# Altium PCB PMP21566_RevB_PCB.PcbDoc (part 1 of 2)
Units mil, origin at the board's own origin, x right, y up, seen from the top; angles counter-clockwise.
Board outline 4339 x 2011 mil, 4 copper layers (Top Layer1, Layer2, Layer3, Bottom Layer4), stack 60.4 mil thick; 97 components, 43 nets, 239 pads, 687 vias.
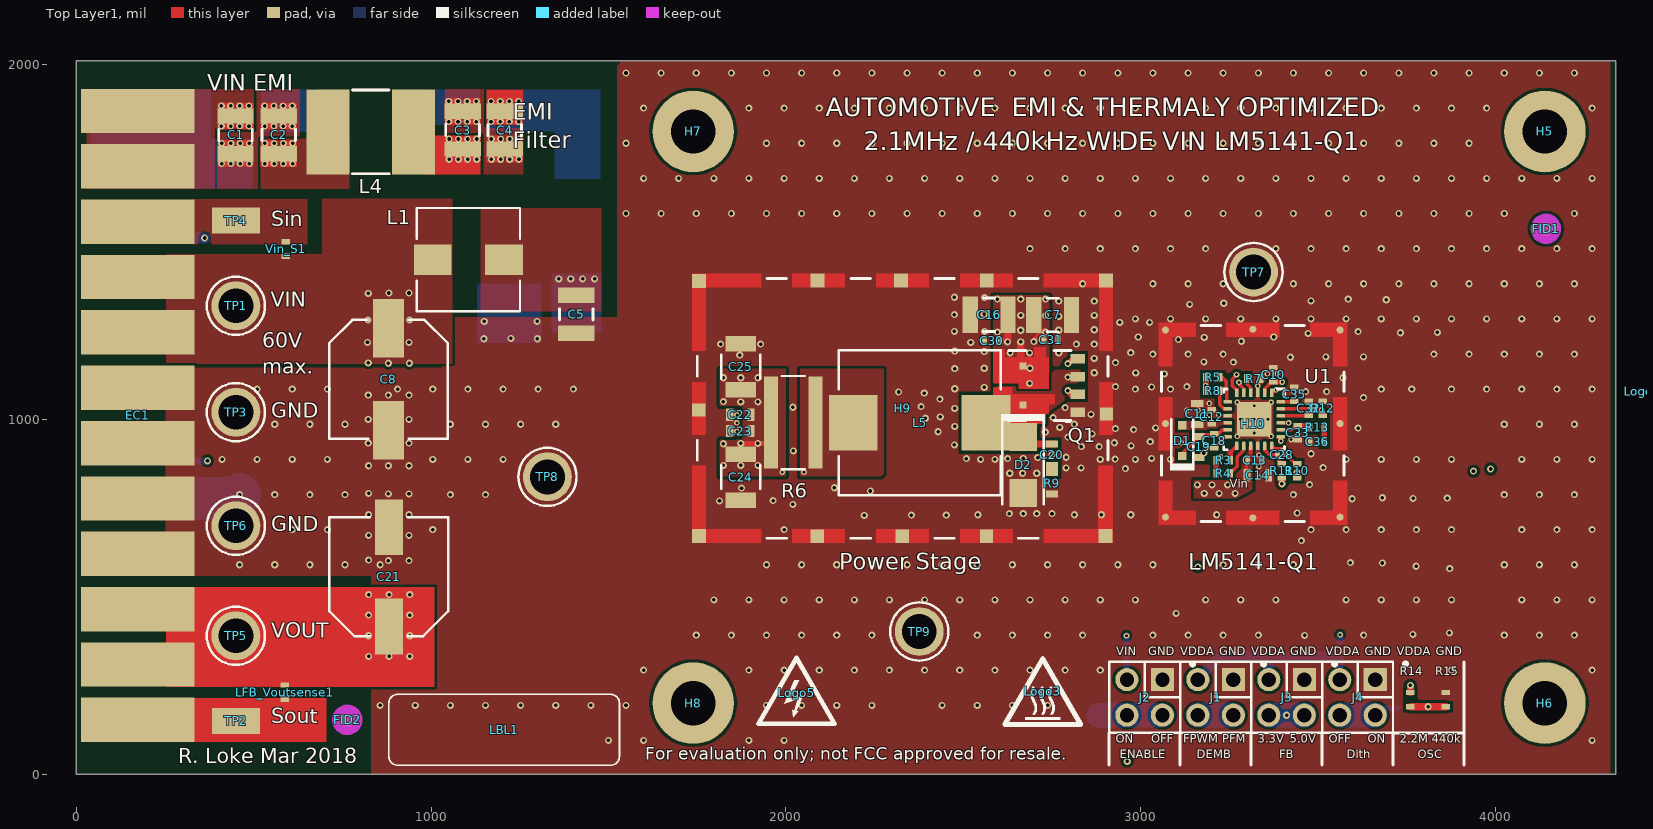
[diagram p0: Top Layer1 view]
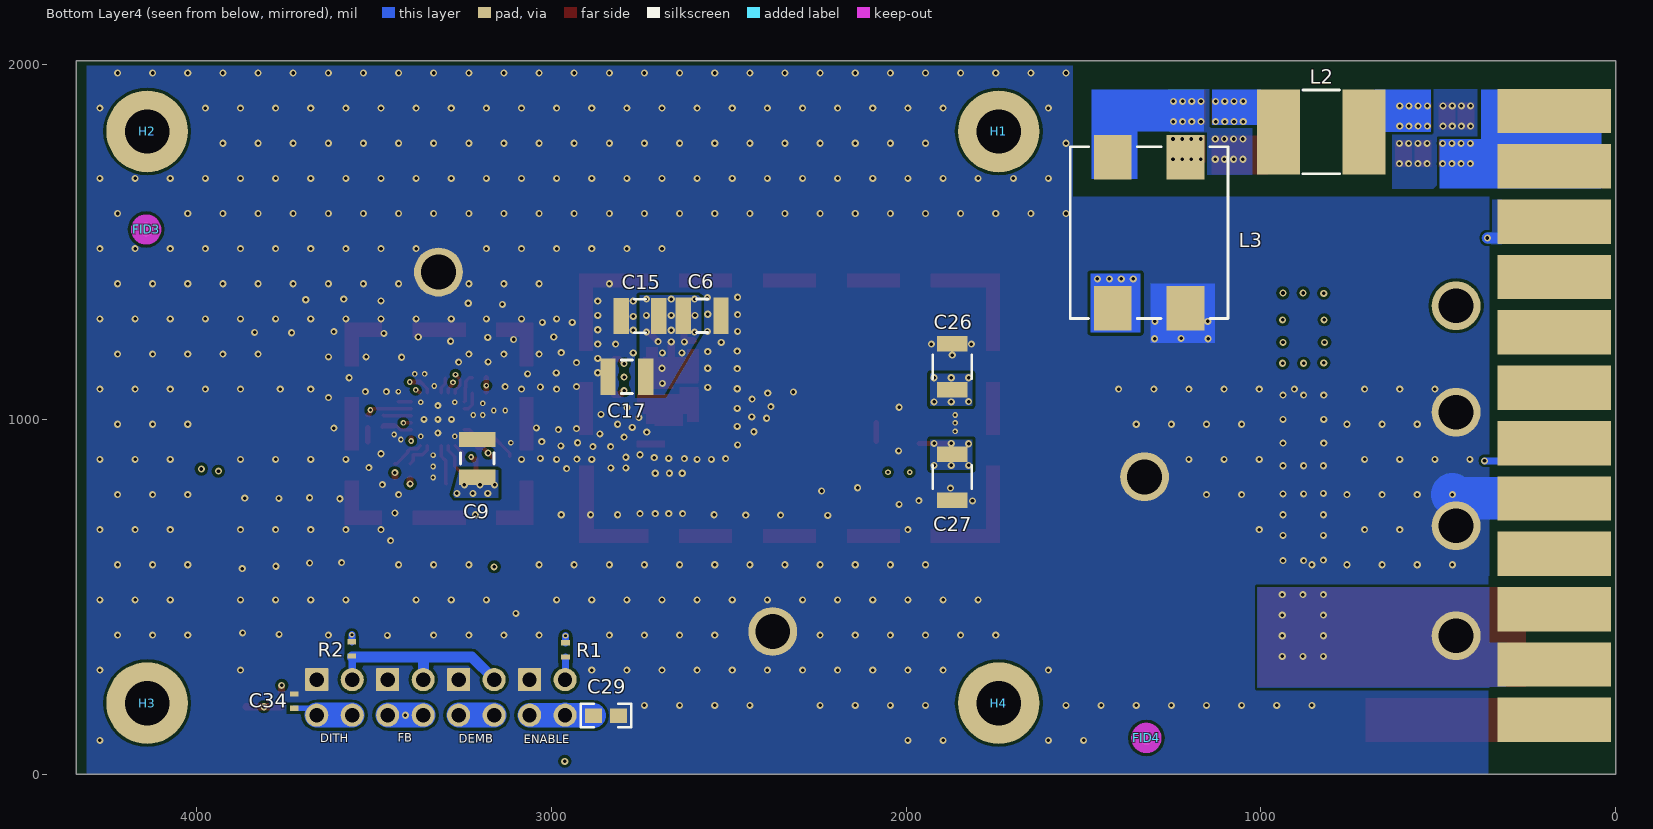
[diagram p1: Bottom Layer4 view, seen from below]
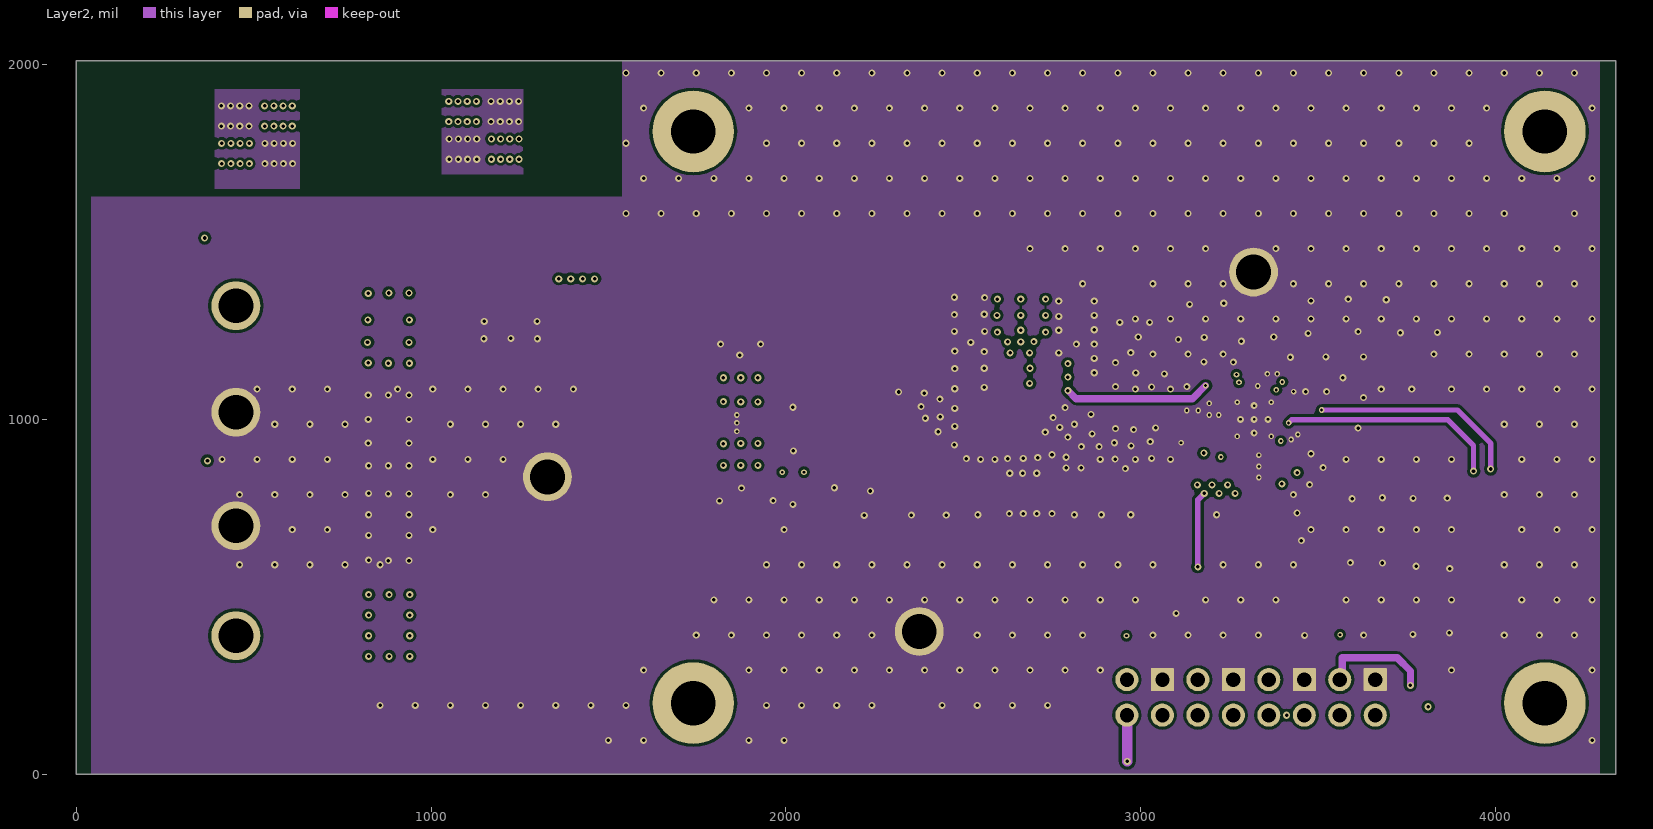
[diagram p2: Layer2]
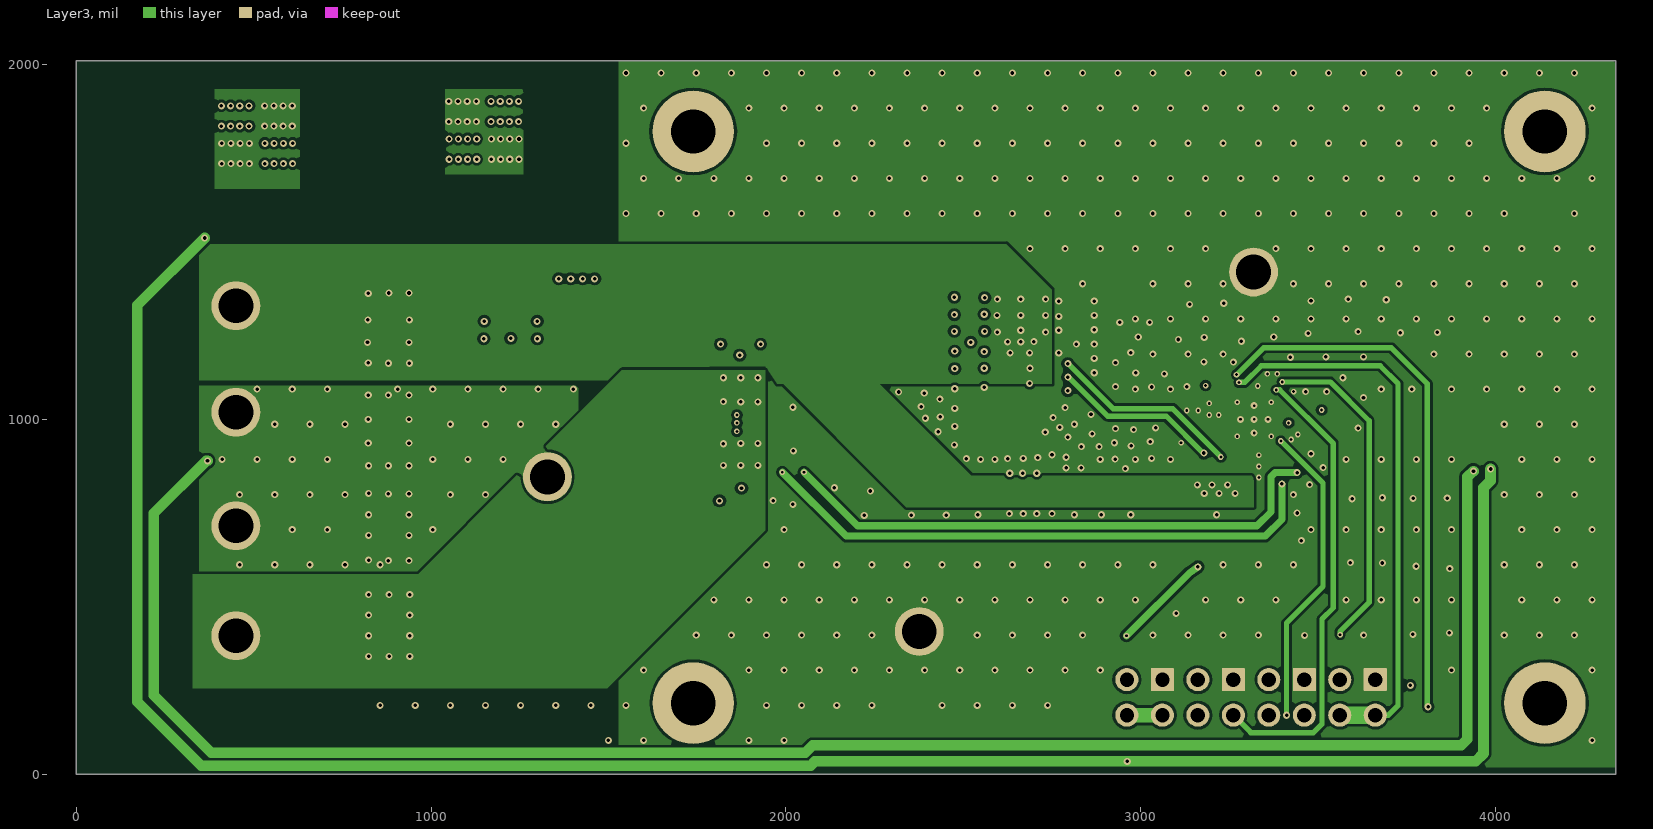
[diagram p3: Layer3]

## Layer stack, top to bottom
Top Solder: solder mask 0.4, Solder Resist, Dk 3.5
Top Layer1: signal copper 2.8
Dielectric1: core 5, FR-4, Dk 4.2
Layer2: signal copper 1.4
Dielectric 3: prepreg 42, FR4, Dk 4.2
Layer3: signal copper 1.4
Dielectric 2: core 5, FR4, Dk 4.2
Bottom Layer4: signal copper 2.8
Bottom Solder: solder mask 0.4, Solder Resist, Dk 3.5

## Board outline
0,0 0,2011 4339,2011 4339,0

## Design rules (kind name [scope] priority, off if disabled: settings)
Clearance Clearance_Poly [InPolygon] p1: gap=8 ignorepadtopadclearanceinfootprint=FALSE
Clearance Clearance_1 [All] p2: gap=6 ignorepadtopadclearanceinfootprint=FALSE
ComponentClearance [All] p1: gap=10 collisioncheckmode=3 verticalgap=-1 showdistances=TRUE
FabricationTestPointUsage TestPointUsage [All] p1: valid=0 allowmultiple=FALSE
FabricationTestpoint Testpoint [All] p1: side=3 testpointundercomponent=TRUE minsize=40 maxsize=100 preferedsize=60 minholesize=20 maxholesize=40 preferedholesize=32 testpointgrid=1 allowsidetop=TRUE allowsidebottom=TRUE usegrid=TRUE gridtolerance=0.01
HoleSize [All] p1: absolutevalues=TRUE maxlimit=247 minlimit=7.87 maxpercent=80.000 minpercent=20.000
MinimumSolderMaskSliver [All] p1: minsoldermaskwidth=3
PasteMaskExpansion PasteMaskExpansion_1 [InComponent('P1')] p1: expansion=-150
PasteMaskExpansion [All] p2: expansion=0
PlaneConnect [All] p1: planeconnectstyle=Relief reliefexpansion=15 reliefentries=4 reliefconductorwidth=5 reliefairgap=5
PolygonConnect [All] p1: connectstyle=Direct reliefconductorwidth=10 reliefentries=4 polygonreliefangle="90 Angle" airgapwidth=10
RoutingVias [All] p1: holewidth=10 width=20 viastyle="Through Hole" minholewidth=7.87 minwidth=16 maxholewidth=15 maxwidth=50
SilkToBoardRegionClearance [Not ((IsComment or IsDesignator) And (Hide <> 'False')) and not InRegion(1000,500,4000,800)] p1:
SilkToSilkClearance [All] p1: silktosilkclearance=2
SilkToSolderMaskClearance SilkscreenOverComponentPads [IsPad] p1: minsilkscreentomaskgap=1 clearancetoexposedcopper=TRUE
SolderMaskExpansion [All] p1: expansion=5
UnRoutedNet [All] p1: checkbadconnections=TRUE
Width [All] p1: maxlimit=150 minlimit=5 preferedwidth=10
19 further rules are at their usual default settings.

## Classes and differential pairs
component class PMP_LM5141_2.1MHZ_RL_RevB: "As short as possble" C1 C2 C3 C4 C5 C6 C7 C8 C9 C10 C11 C12 C13 C14 C15 C16 C17 C18 C19 C20 C21 C22 C23 C24 C25 C26 C27 C28 C29 C30 C31 C32 C33 C34 C35 C36 "Close to Q1" "Close to Q1S" "Close to Q3" "Close to Q3S" "Close to Q5" "Close to Q6" D1 D2 H9 H10 J1 J2 J3 J4 L1 L2 L3 L4 L5 L6 LFB_Voutsense1 Q1 R1 R2 R3 R4 R5 R6 R7 R8 R9 R10 R11 R12 R13 R14 R15 R25 R26 TP1 TP2 TP3 TP4 TP5 TP6 TP7 TP8 TP9 TP14 U1 Vin_S1 ZX1 ZX2 ZX3
component class PMP_LM5141_2.1MHZ_RL_RevB_HW: !PCB1 FID1 FID2 FID3 FID4 H1 H2 H3 H4 H5 H6 H7 H8 LBL1 Logo1 Logo2 Logo3 Logo4 Logo5
component class FiducialMark: FID1 FID2 FID3 FID4
component class Label: LBL1
component class AssemblyNote: ZX1 ZX2 ZX3
component class Header: J1 J2 J3 J4

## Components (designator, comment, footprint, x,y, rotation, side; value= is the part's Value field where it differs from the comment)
C1 "GRM32ER71J106KA12L" 1210_270L 449,1801.49 r270 top value=10uF
C2 "GRM32ER71J106KA12L" 1210_270L 571,1801.49 r270 top value=10uF
C3 "GRM32ER71J106KA12L" 1210_270L 1089,1815 r270 top value=10uF
C4 "GRM32ER71J106KA12L" 1210_270L 1208,1815 r270 top value=10uF
C5 "GRM32ER71J106KA12L" 1210_270L 1409,1296 r270 top value=10uF
C6 "GRM32ER71J106KA12L" 1210_270L 2575,1292 r180 bottom value=10uF
C7 "GRM32ER71J106KA12L" 1210_270L 2752,1294 r0 top value=10uF
C8 "EMVE630ADA470MHA0G" CAPSMT_62_HA0 880,1113 r270 top value=47uF
C9 "GRM32ER71J106KA12L" 1210_270L 3209,890 r90 bottom value=10uF
C10 "C0402C104K4RACAUTO" 0402S 3373,1126 r270 top value=0.1uF
C11 "GRM188Z71C475KE21D" 0603S 3159,1015 r90 top value=4.7uF
C12 "C0402C104K4RACAUTO" 0402S 3200,1007 r270 top value=0.1uF
C13 "GRM155R72A472KA01D" 0402S 3321,884 r0 top value=4700pF
C14 "GCJ188R72A104KA01D" 0603S 3330,842 r0 top value=0.1uF
C15 "GRM32ER71J106KA12L" 1210_270L 2750,1291 r0 bottom value=10uF
C16 "GRM32ER71J106KA12L" 1210_270L 2573,1295 r180 top value=10uF
C17 "GRM32ER71J106KA12L" 1210_270L 2787,1120 r0 bottom value=10uF
C18 "C1005X7R1H683K050BB" 0402S 3207,939 r270 top value=0.068uF
C19 "CGA3E3X7R1H474K080AB" 0603S 3163,922 r90 top value=0.47uF
C20 "06031C102JAT2A" 0603S 2750,900 r270 top value=1000pF
C21 "EEE-FK1E221P" SM_RADIAL_F 881,556 r90 top value=220uF
C22 "GRM188Z71C475KE21D" 0603S 1872,1013 r180 top value=4.7uF
C23 "GRM188Z71C475KE21D" 0603S 1872,967 r180 top value=4.7uF
C24 "LMK325ABJ107MMHT" 1210_280 1873,837 r270 top value=100uF
C25 "LMK325ABJ107MMHT" 1210_280 1873,1148 r90 top value=100uF
C26 "LMK325ABJ107MMHT" 1210_280 1870,1148 r90 bottom value=100uF
C27 "LMK325ABJ107MMHT" 1210_280 1870,837 r270 bottom value=100uF
C28 "GRM0335C1H330JA01D" 0201L 3397,900 r180 top value=33pF
C29 "1.5ms delay at 12Vin" 0603M 2846,165 r180 bottom value=0.022uF
C30 "GRM155R72A472KA01D" 0402S 2580,1222 r180 top value=4700pF
C31 "GRM155R72A472KA01D" 0402S 2747,1224 r0 top value=4700pF
C32 "C1005X7R1H683K050BB" 0402S 3473,1031 r90 top value=0.068uF
C33 "GRM1555C1H220JA01D" 0402S 3443,962 r270 top value=22pF
C34 "C0402C103J5RACTU" 0402S 3725,206 r270 bottom value=0.01uF
C35 "CGA2B3X7R1H103K050BB" 0402S 3433,1071 r90 top value=0.01uF
C36 "CGA2B3X7R1H103K050BB" 0402S 3497,937 r180 top value=0.01uF
D1 "PMEG6010CEJ,115" SOD-323F 3117,940 r90 top value=60V
D2 "SSA210" SMA 2668.98,871.26 r270 top value=100V
EC1 "305-024-521-201" Edge_Connector_EDAC_12x2 146,1011 r270 top
FID1 "Fiducial" Fiducial10-20 4142,1537 r0 top
FID2 "Fiducial" Fiducial10-20 764,153 r0 top
FID3 "Fiducial" Fiducial10-20 4142,1535 r180 bottom
FID4 "Fiducial" Fiducial10-20 1323,102 r180 bottom
H1 "1902C" Keystone_1902C 1738.62,1811.26 r0 bottom
H2 "1902C" Keystone_1902C 4138.62,1811.26 r0 bottom
H3 "1902C" Keystone_1902C 4138.62,200.26 r0 bottom
H4 "1902C" Keystone_1902C 1738.98,200.26 r0 bottom
H5 "PMSSS 440 0025 PH" B_F_PMSSS4400025PH 4138.98,1811.26 r270 top
H6 "PMSSS 440 0025 PH" B_F_PMSSS4400025PH 4138.98,200.26 r270 top
H7 "PMSSS 440 0025 PH" B_F_PMSSS4400025PH 1738.98,1811.26 r270 top
H8 "PMSSS 440 0025 PH" B_F_PMSSS4400025PH 1738.98,200.26 r270 top
H9 "BMI-S-209-F" Laird_BMI-S-209-F 2329,1031 r180 top
H10 "BMI-S-201-F" Laird_BMI-S-201-F 3316,988 r0 top
J1 "DEMB" TSW-102-07-G-D 3211.07,216.25 r180 top
J2 "EN" TSW-102-07-G-D 3011.07,216.25 r180 top
J3 "FB" TSW-102-07-G-D 3411.07,216.25 r180 top
J4 "Dith" TSW-102-07-G-D 3611.07,216.25 r180 top
L1 "744314150" WE-HCI_7050 1105,1450 r180 top value=1.5uH
L2 "HR2220V801R-10" 2220_390 830,1810 r0 bottom value="800 ohm"
L3 "ACM1211-701-2PL-TL01" TDK_ACM1211 1315,1526 r180 bottom
L4 "HR2220V801R-10" 2220_390 830,1810 r0 top value="800 ohm"
L5 "IHLP4040DZER2R0M11" IHLP-4040DZ 2376.98,990.26 r180 top value=2uH
LBL1 "" Label_650x200 1206,125 r0 top
LFB_Voutsense1 "BLM15AX100SN1D" 0402S 588,231 r270 top value="10 ohm"
Logo1 "FCC disclaimer" FCC_disclaimer 4415,1079 r90 top
Logo3 "CAUTION HOT SURFACE" IEC_HotSurface_Small 2724,233 r0 top
Logo5 "DANGER HIGH VOLTAGE" IEC_HighVoltage_Small 2030,230 r0 top
Q1 "SQJB60EP-T1_GE3" PowerPAK_SO-8L_Dual 2715.98,1095.26 r180 top value=60V
R1 "CRCW0402100KFKED" 0402S 2960,350 r90 bottom value=100k
R2 "CRCW0402100KFKED" 0402S 3562,353 r90 bottom value=100k
R3 "RMCF0402JT10R0" 0402S 3232,885 r180 top value=10.0
R4 "RK73Z1ETTP" 0402S 3232,848 r180 top value=0
R5 "RK73Z1ETTP" 0402S 3203,1118 r180 top value=0
R6 "KRL6432E-M-R006-F-T1" 2512_WIDE 2021,991 r180 top value=0.006
R7 "2.1MHz" 0402S 3319,1115 r0 top value=51.1k
R8 "RK73Z1ETTP" 0402S 3203,1080 r180 top value=0
R9 "CRCW06031R00JNEA" 0603S 2750,820 r90 top value=1.0
R10 "RMCF0402FT49R9" 0402S 3441,855 r90 top value=49.9
R11 "RK73Z1ETTP" 0402S 3398,855 r90 top value=0
R12 "Turns ON at 6Vin" 0402S 3513,1031 r270 top value=49.9k
R13 "CRCW04025K49FKED" 0402S 3497,977 r180 top value=5.49k
R14 "2.2MHz" 0402S 3760,210 r90 top value=0
R15 "DNP" 0402S 3860,210 r90 top value=0
TP1 "Vin" Keystone1598-2 450,1320 r180 top value=Triple
TP2 "S1751-46" Harwin_S1751-46 450,150 r0 top
TP3 "GND" Keystone1598-2 450,1020 r180 top value=Triple
TP4 "S1751-46" Harwin_S1751-46 450,1560 r180 top
TP5 "Vout" Keystone1598-2 450,390 r180 top value=Triple
TP6 "GND" Keystone1598-2 450,700 r180 top value=Triple
TP7 "GND" Keystone1598-2 3318,1415 r90 top value=Triple
TP8 "GND" Keystone1598-2 1328,838 r90 top value=Triple
TP9 "GND" Keystone1598-2 2376,402 r90 top value=Triple
U1 "LM5141QRGERQ1" RGE0024J 3320,1000 r270 top
Vin_S1 "BLM15AX100SN1D" 0402S 590,1480 r270 top value="10 ohm"
ZX1 "VIN = 9...36V DC, 5.5V...42V Abs max." AssemblyNote 170,2390 r0 top
ZX2 "VOUT = 3.3VDC at 10A" AssemblyNote 170,2460 r0 top
ZX3 "Fsw = 2.2MHz" AssemblyNote 170,2530 r0 top

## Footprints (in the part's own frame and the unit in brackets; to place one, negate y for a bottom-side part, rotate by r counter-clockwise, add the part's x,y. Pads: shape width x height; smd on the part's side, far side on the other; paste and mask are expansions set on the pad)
0201L [mm] "Data from Kemet datasheet CC101_COM dated 7/28/11"
  rect 0.36x0.32 smd mask+0.048: 1(-0.28,0) 2(0.28,0)
  body extent -0.31,-0.16 0.31,0.16, height 0.26
0402S [mil] "Based on C0402S footprint from PADS legacy"
  rect 15x24 smd: 1(-20,0) 2(20,0)
  body extent -22,-12 22,12, height 24
0603M [mm] "0603 from SM-752 data"
  rect 1.2x1.05 smd: 1(-0.9,0) 2(0.9,0)
  silkscreen extent -1.82,-0.84 1.82,0.84, body extent -0.87,-0.47 0.87,0.47, height 1
0603S [mil]
  rect 20x35 smd: 1(-30,0) 2(30,0)
  body extent -34,-19 34,19, height 39
1210_270L [mm] "1210"
  rect 1.1x2.6 smd: 1(-1.35,0) 2(1.35,0)
  silkscreen extent -0.4,-1.2 0.4,1.2, body extent -1.7,-1.35 1.7,1.35, height 2.7
1210_280 [mm] "SMD, 2-Leads, Body 3.6x2.8mm, Height 2.8mm"
  rect 1.1x2.2 smd: 1(-1.65,0) 2(1.65,0)
  silkscreen extent -0.84,-1.4 0.84,1.4, body extent -1.8,-1.4 1.8,1.4, height 2.8
2220_390 [mm] "Laird recommended land pattern"
  rrect3% 3.07x6.1 smd: 1(-3.06,0) 2(3.06,0)
  silkscreen extent -1.3,-3 1.3,3, body extent -2.8,-2.54 2.79,2.54, height 3.9
2512_WIDE [mm] "Ohmite recommended land pattern"
  rect 1x6.6 smd: 1(-1.6,0) 2(1.6,0)
  silkscreen extent -0.82,-3.32 0.82,3.35, body extent -1.65,-3.25 1.65,3.25, height 0.7
AssemblyNote [mil] "Assembly Note"
B_F_PMSSS4400025PH [mil] "MACHINE SCREW PAN PHILLIPS 4-40"
  round 230 hole 125: 1(0,0)
  body extent -109,-109 110,110, height 79
CAPSMT_62_HA0 [mm] "8 x 10mm:  Chemi-Con HA0"
  rect 4.2x2.2 smd: 1(-3.65,0) 2(3.65,0)
  silkscreen extent -4.25,-4.25 4.25,4.25, body extent -4.25,-4.25 4.25,4.25, height 10.5
Edge_Connector_EDAC_12x2 [mil] "Footprint to mate to EDAC 305 Series Edge connector"
  rect 125x320 smd far side paste-260: 1(858,27) 2(702,27) 3(546,27) 4(390,27) 5(234,27) 6(78,27) 7(-78,27) 8(-234,27) 9(-390,27) 10(-546,27) 11(-702,27) 12(-858,27)
  rect 125x320 smd paste-260: A(858,27) B(702,27) C(546,27) D(390,27) E(234,27) F(78,27) H(-78,27) J(-234,27) K(-390,27) L(-546,27) M(-702,27) N(-858,27)
FCC_disclaimer [mil]
Fiducial10-20 [mm]
  round 1 smd mask+0.5: 1(0,0)
  Top Layer1 keep-out circle w1.178: c0,0 r0.5
Harwin_S1751-46 [mm] "Test Point, Body 3.25x1.65mm"
  rect 3.45x1.85 smd: 1(0,0)
  body extent -1.62,-0.82 1.63,0.82, height 2.05
IEC_HighVoltage_Small [mil]
  silkscreen extent -107,-88 107,97
IEC_HotSurface_Small [mil]
  silkscreen extent -107,-93 107,92
IHLP-4040DZ [mm] "Vishay Dale recommended land pattern.  Document 34192 rev 04-Jul-08"
  rect 3.5x4 smd: 1(-4.75,0) 2(4.75,0)
  silkscreen extent -5.8,-5.2 5.8,5.2, body extent -5.75,-5.15 5.75,5.15, height 4
Keystone1598-2 [mm] "Triple Turret"
  round 3.5 hole 2.5: 1(0,0)
  silkscreen extent -2.08,-2.08 2.08,2.08, body extent -1.6,-1.6 1.59,1.6, height 7.72
Keystone_1902C [mil] "Hex Standoff, 4-40 threaded, nylon"
  round 1 on Mech4: 0(0,0)
  body extent -145,-126 146,126, height 501
Label_650x200 [mil] "Thermal Transfer Label"
  round 1 on Mech13: 0(0,0)
  silkscreen extent -325,-100 325,100, body extent -325,-100 325,100, height 1
Laird_BMI-S-201-F [mm] "SMD, 8-Leads, Body 13.06x14.02mm"
  round 0.5 smd: 1(-6.25,-6.694) 1(-6.25,0) 1(-6.25,6.694) 1(0,-6.75) 1(0,6.75) 1(6.25,-6.694) 1(6.25,0) 1(6.25,6.694)
  Top Layer1 region: -1.9,-7.23 -1.9,-6.23 1.9,-6.23 1.9,-7.23
  Top Layer1 region: 4.1,-7.23 4.1,-6.23 5.75,-6.23 5.75,-4.1 6.75,-4.1 6.75,-7.23
  Top Layer1 region: 5.75,-1.9 6.75,-1.9 6.75,1.9 5.75,1.9
  Top Layer1 region: 4.1,6.23 4.1,7.23 6.75,7.23 6.75,4.1 5.75,4.1 5.75,6.23
  Top Layer1 region: -1.9,6.23 1.9,6.23 1.9,7.23 -1.9,7.23
  Top Layer1 region: -6.75,4.1 -5.75,4.1 -5.75,6.23 -4.1,6.23 -4.1,7.23 -6.75,7.23
  Top Layer1 region: -6.75,-1.9 -6.75,1.9 -5.75,1.9 -5.75,-1.9
  Top Layer1 region: -6.75,-7.23 -6.75,-4.1 -5.75,-4.1 -5.75,-6.23 -4.1,-6.23 -4.1,-7.23
  silkscreen extent -6.53,-7.01 6.53,7.01, body extent -6.65,-7.13 6.66,7.14, height 2.54
Laird_BMI-S-209-F [mm] "LAIRD"
  rect 0.95x0.95 smd: 1(-14.6,0.4) 1(-6,9.15) 1(0.025,9.15) 1(6.1,9.15) 1(14.6,0.125)
  rect 1x1 smd: 1(-14.575,-9.15) 1(-14.525,9.15) 1(-6.025,-9.15) 1(0.125,-9.15) 1(6.075,-9.15) 1(14.575,-9.125) 1(14.575,9.15)
  Top Layer1 region: 10.105,8.65 15.085,8.65 15.085,9.65 10.105,9.65
  Top Layer1 region: 4.105,8.65 7.905,8.65 7.905,9.65 4.105,9.65
  Top Layer1 region: -1.895,8.65 1.905,8.65 1.905,9.65 -1.895,9.65
  Top Layer1 region: -7.895,8.65 -4.095,8.65 -4.095,9.65 -7.895,9.65
  Top Layer1 region: -14.575,8.65 -10.095,8.65 -10.095,9.65 -14.575,9.65
  Top Layer1 region: -15.075,4.1 -13.975,4.1 -13.975,9.65 -15.075,9.65
  Top Layer1 region: -15.075,-1.9 -14.075,-1.9 -14.075,1.9 -15.075,1.9
  Top Layer1 region: -15.075,-9.65 -14.075,-9.65 -14.075,-4.1 -15.075,-4.1
  Top Layer1 region: 14.085,4.1 15.085,4.1 15.085,9.65 14.085,9.65
  Top Layer1 region: 14.085,-1.9 15.085,-1.9 15.085,1.9 14.085,1.9
  Top Layer1 region: 14.085,-9.65 15.085,-9.65 15.085,-4.1 14.085,-4.1
  Top Layer1 region: -14.525,-9.65 -10.095,-9.65 -10.095,-8.65 -14.525,-8.65
  Top Layer1 region: -7.895,-9.65 -4.095,-9.65 -4.095,-8.65 -7.895,-8.65
  Top Layer1 region: -1.895,-9.65 1.905,-9.65 1.905,-8.65 -1.895,-8.65
  Top Layer1 region: 4.105,-9.65 7.905,-9.65 7.905,-8.65 4.105,-8.65
  Top Layer1 region: 10.105,-9.65 15.085,-9.65 15.085,-8.65 10.105,-8.65
  silkscreen extent -14.7,-9.3 14.7,9.3, body extent -14.68,-9.25 14.68,9.25, height 7
PowerPAK_SO-8L_Dual [mm] "SMD, 6-Leads, Body 4.9x4.37mm"
  rect 1.02x0.68 smd: 1(-2.715,1.905) 2(-2.715,0.635) 3(-2.715,-0.635) 4(-2.715,-1.905)
  rect 0.5x0.5 smd paste+0 mask+0.102: 5(1.2,-1.4) 6(1.2,1.4)
  Top Layer1 region: -0.405,2.725 -0.405,2.015 -0.635,2.015 -0.635,0.955 2.115,0.955 2.115,0.215 3.325,0.215 3.325,2.6 2.515,2.6 2.515,2.015 0.405,2.015 0.405,2.725
  Top Layer1 region: -0.635,0.215 1.505,0.215 1.505,-0.295 3.325,-0.295 3.325,-2.6 2.515,-2.6 2.515,-2.015 0.405,-2.015 0.405,-2.725 -0.405,-2.725 -0.405,-2.015 -0.635,-2.015
  silkscreen extent -2.24,-2.5 2.23,2.7, body extent -2.28,-2.55 2.28,2.55, height 1.27
RGE0024J [mm] "QFN, 24-Leads, Body 4x4mm, Pitch 0.5mm, Thermal Pad 2.45x2.45mm, TI Recommended"
  rrect40% 0.6x0.25 smd: 1(-1.9,1.25) 2(-1.9,0.75) 3(-1.9,0.25) 4(-1.9,-0.25) 5(-1.9,-0.75) 6(-1.9,-1.25) 13(1.9,-1.25) 14(1.9,-0.75) 15(1.9,-0.25) 16(1.9,0.25) 17(1.9,0.75) 18(1.9,1.25)
  rrect40% 0.25x0.6 smd: 7(-1.25,-1.9) 8(-0.75,-1.9) 9(-0.25,-1.9) 10(0.25,-1.9) 11(0.75,-1.9) 12(1.25,-1.9) 19(1.25,1.9) 20(0.75,1.9) 21(0.25,1.9) 22(-0.25,1.9) 23(-0.75,1.9) 24(-1.25,1.9)
  rrect9% 1.08x1.08 on Top Paste: 25(-0.64,0.64) 25(-0.64,-0.64) 25(0.64,0.64) 25(0.64,-0.64)
  rrect4% 2.45x2.45 smd paste-1.225: 25(0,0)
  silkscreen extent -2.17,-2.17 2.17,2.17, body extent -2,-2 2,2, height 1
SM_RADIAL_F [mm] "8 x 10.2mm:  Panasonic F"
  rect 4x2 smd: 1(-3.55,0) 2(3.55,0)
  silkscreen extent -4.25,-4.25 4.25,4.25, body extent -4.25,-4.25 4.25,4.25, height 10.5
SMA [mm] "Molded Diode, 2-Leads, Body 4.3x2.6mm, IPC Medium Density, based on OnSemi component dimensions and land pattern"
  rect 2x2 smd: 1(-2,0) 2(2,0)
  silkscreen extent -3.66,-1.57 2.79,1.57, body extent -2.6,-1.3 2.6,1.3, height 2.42
SOD-323F [mm] "NXP recommended land pattern"
  rect 0.6x0.6 smd paste-0.05: 1(-1.1,0) 2(1.1,0)
  silkscreen extent -2.13,-0.86 1.53,0.86, body extent -1.35,-0.67 1.35,0.68, height 0.79
TDK_ACM1211 [mm] "SMT, 4-Leads, Body 12x11mm"
  rect 2.7x3.2 smd: 1(-2.6,5.4) 2(2.6,5.4) 3(2.6,-5.4) 4(-2.6,-5.4)
  silkscreen extent -5.65,-6.15 5.65,6.15, body extent -5.65,-6.15 5.65,6.15, height 6
TSW-102-07-G-D [mm] "Samtec 100mil, 2x2, 230 mil above insulator"
  rrect6% 1.65x1.65 hole 1.016: 1(-1.27,-1.27)
  round 1.65 hole 1.016: 2(-1.27,1.27) 3(1.27,-1.27) 4(1.27,1.27)
  silkscreen extent -3.57,-2.54 2.54,2.54, body extent -2.54,-2.54 2.54,2.54, height 8.38
WE-HCI_7050 [mm] "Wurth Electronik recommended land pattern"
  rect 2.7x2.2 smd: 1(-2.55,0) 2(2.55,0)
  silkscreen extent -3.7,-3.7 3.7,3.7, body extent -3.6,-3.6 3.6,3.6, height 5

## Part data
C1 C2 C3 C4 C5 C6 C7 C9 C15 C16 C17: library part CMP-0009229-2, "CAP, CERM, 10 uF, 63 V, +/- 10%, X7R, 1210", Cap_Case=1210, Manufacturer=MuRata, Supplier Part Number 1=490-9970-1-ND, TempCo=X7R, Tolerance_%=10%, Value1=Unknown, Value2=63V, ValueDisplayed=10uF
C8: library part CMP-0011301-2, "CAP, AL, 47 uF, 63 V, +/- 20%, SMD", Cap_Case=HA0, Manufacturer=Chemi-Con, Supplier Part Number 1=565-2267-1-ND, Tolerance_%=20%, Value1=Unknown, Value2=63V, ValueDisplayed=47uF
C10 C12: library part CMP-0006237-2, "CAP, CERM, 0.1 uF, 16 V, +/- 10%, X7R, AEC-Q200 Grade 1, 0402", Cap_Case=0402, Manufacturer=Kemet, Supplier Part Number 1=399-6828-1-ND, TempCo=X7R, Tolerance_%=10%, Value1=Unknown, Value2=16V, ValueDisplayed=0.1uF
C11 C22 C23: library part CMP-0064936-4, "CAP, CERM, 4.7 uF, 16 V,+/- 10%, X7R, 0603", Cap_Case=0603, Manufacturer=MuRata, TempCo=X7R, Tolerance_%=10%, Value1=Unknown, Value2=16V, ValueDisplayed=4.7uF
C13 C30 C31: library part CMP-0006712-2, "CAP, CERM, 4700 pF, 100 V, +/- 10%, X7R, 0402", Cap_Case=0402, Manufacturer=MuRata, Supplier Part Number 1=490-3885-1-ND, TempCo=X7R, Tolerance_%=10%, Value1=Unknown, Value2=100V, ValueDisplayed=4700pF
C14: library part CMP-0064935-4, "CAP, CERM, 0.1 uF, 100 V,+/- 10%, X7R, AEC-Q200 Grade 1, 0603", Cap_Case=0603, Manufacturer=MuRata, Supplier Part Number 1=490-13420-1-ND, TempCo=X7R, Tolerance_%=10%, Value1=Unknown, Value2=100V, ValueDisplayed=0.1uF
C18 C32: library part CMP-0006299-2, "CAP, CERM, 0.068 uF, 50 V, +/- 10%, X7R, 0402", Cap_Case=0402, Manufacturer=TDK, Supplier Part Number 1=445-5930-1-ND, TempCo=X7R, Tolerance_%=10%, Value1="0.05606 ohm", Value2=50V, ValueDisplayed=0.068uF
C19: library part CMP-0007096-4, "CAP, CERM, 0.47 uF, 50 V, +/- 10%, X7R, AEC-Q200 Grade 1, 0603", Cap_Case=0603, Manufacturer=TDK, Supplier Part Number 1=810-CGA3E3X7R1H474K080AB, TempCo=X7R, Tolerance_%=10%, Value1="0.01064 ohm", Value2=50V, ValueDisplayed=0.47uF
C20: library part CMP-0006723-4, "CAP, CERM, 1000 pF, 100 V, +/- 5%, X7R, 0603", Cap_Case=0603, Manufacturer=AVX, Supplier Part Number 1=478-3698-1-ND, TempCo=X7R, Tolerance_%=5%, Value1="0.276 ohm", Value2=100V, ValueDisplayed=1000pF
C21: library part CMP-0010714-1, "CAP, AL, 220 uF, 25 V, +/- 20%, 0.16 ohm, AEC-Q200 Grade 2, SMD", Cap_Case=F, Manufacturer=Panasonic, Supplier Part Number 1=PCE3800CT-ND, Tolerance_%=20%, Value1="0.16 ohm", Value2=25V, ValueDisplayed=220uF
C24 C25: "CAP, CERM, 100 µF, 10 V, +/- 20%, X5R, AEC-Q200 Grade 3, 1210", Cap_Case=1210, Manufacturer="Taiyo Yuden", Supplier Part Number 1=587-3432-1-ND, TempCo=X5R, Tolerance_%=20, Value1=Unknown, Value2=10V, ValueDisplayed=100µF
C26 C27: "CAP, CERM, 100 µF, 10 V,+/- 20%, X5R, AEC-Q200 Grade 3, 1210", Cap_Case=1210, Manufacturer="Taiyo Yuden", Supplier Part Number 1=587-3432-1-ND, TempCo=X5R, Tolerance_%=20, Value2=10V, ValueDisplayed=100µF
C28: "CAP, CERM, 33 pF, 50 V,+/- 5%, C0G/NP0, 0201", Cap_Case=0201, Manufacturer=MuRata, Supplier Part Number 1=490-6126-1-ND, TempCo=C0G/NP0, Tolerance_%=5, Value2=50V, ValueDisplayed=33pF
C29: library part CMP-0007086-4, "CAP, CERM, 0.022 uF, 100 V, +/- 10%, X7R, AEC-Q200 Grade 1, 0603", Cap_Case=0603, Manufacturer=TDK, PartNumber=CGA3E2X7R2A223K080AA, Supplier Part Number 1=445-5814-1-ND, TempCo=X7R, Tolerance_%=10%, Value1="0.083542 ohm", Value2=100V, ValueDisplayed=0.022uF
C33: "CAP, CERM, 22 pF, 50 V,+/- 5%, C0G/NP0, 0402", Cap_Case=0402, Manufacturer=MuRata, Supplier Part Number 1=81-GRM1555C1H220JA1D, TempCo=C0G/NP0, Tolerance_%=5, Value2=50V, ValueDisplayed=22pF
C34: library part CMP-0006236-2, "CAP, CERM, 0.01 uF, 50 V, +/- 5%, X7R, 0402", Cap_Case=0402, Manufacturer=Kemet, Supplier Part Number 1=399-7758-1-ND, TempCo=X7R, Tolerance_%=5%, Value1=Unknown, Value2=50V, ValueDisplayed=0.01uF
C35 C36: library part CMP-0006324-2, "CAP, CERM, 0.01 uF, 50 V, +/- 10%, X7R, AEC-Q200 Grade 1, 0402", Cap_Case=0402, Manufacturer=TDK, Supplier Part Number 1=445-6893-1-ND, TempCo=X7R, Tolerance_%=10%, Value1="0.333065 ohm", Value2=50V, ValueDisplayed=0.01uF
D1: "Diode, Schottky, 60 V, 1 A, SOD-323F", Manufacturer="NXP Semiconductor", Supplier Part Number 1=568-4138-1-ND, Value1=1A, Value2=0.66V
D2: library part CMP-0028811-1, "Diode, Schottky, 100 V, 2 A, AEC-Q101, SMA", Manufacturer="Fairchild Semiconductor", Supplier Part Number 1=SSA210CT-ND, Value1=2A, Value2=0.8V
EC1: "Edge Connector", Manufacturer="Edac Inc."
FID1 FID2 FID3 FID4: "Fiducial mark.  There is nothing to buy or mount.", Manufacturer=N/A
H1 H2 H3 H4: "Standoff, Hex, 0.5\"L #4-40 Nylon", Alternate Manufacturer=-, Manufacturer=Keystone, Supplier Part Number 1=1902CK-ND
H5 H6 H7 H8: library part CMP-0003715-1, "MACHINE SCREW PAN PHILLIPS 4-40", Manufacturer="B&F Fastener Supply", Supplier Part Number 1=H703-ND
H9: library part CMP-0003727-1, "Standard Surface Mount Shield , Height 7mm", Manufacturer="Laird-Signal Integrity Products"
H10: library part CMP-0003716-1, "EMI SHIELD, 13.66 x 12.70 mm, SMT", Manufacturer="Laird-Signal Integrity Products"
J1 J2 J3 J4: library part CMP-0075404-1, "Header, 100mil, 2x2, Gold, TH", Color=Black, Current_A=6.3A, Manufacturer=Samtec, PartNumber=TSW-102-07-G-D, Supplier Part Number 1=SAM1028-02-ND, Voltage_V=550V
L1: library part CMP-0061018-2, "Inductor, Shielded, Composite, 560 nH, 22 A, 0.00331 ohm, AEC-Q200 Grade 1, SMD", Manufacturer="Wurth Elektronik", Supplier Part Number 1=732-1158-1-ND, Value1="0.0046 ohm", Value2=11A, ValueDisplayed=1.5uH
L2 L4: library part CMP-0003396-1, "Ferrite Bead, 800 ohm @ 100 MHz, 8 A, 2220", Manufacturer="Laird-Signal Integrity Products", Supplier Part Number 1=240-2433-1-ND, Value1="0.01 ohm", Value2=8A, ValueDisplayed="800 ohm"
L3: library part CMP-0013118-2, "Coupled inductor, 8 A, 0.006 ohm, SMD", Manufacturer=TDK, Supplier Part Number 1=445-2212-1-ND
L5: library part CMP-0082371-1, "Inductor, Shielded, 470 nH, 28.5 A, 0.00166 ohm, AEC-Q200 Grade 0, SMD", Manufacturer=Vishay-Dale, Supplier Part Number 1=541-1311-1-ND, Value1="0.0058 ohm", Value2=14A, ValueDisplayed=2uH
LBL1: library part THT-14-423-10, "Thermal Transfer Printable Labels, 0.650\" W x 0.200\" H - 10,000 per roll", Alternate Manufacturer=-, Manufacturer=Brady, Supplier Part Number 1=2065596
LFB_Voutsense1 Vin_S1: "Ferrite Bead, 10 ohm @ 100 MHz, 1.74 A, 0402", Manufacturer=MuRata, Supplier Part Number 1=490-5437-6-ND, Value1="0.015 ohm", Value2=1.74A
Logo1: library part FCC_disclaimer, "FCC_disclaimer"
Logo3: library part IEC_HotSurface, "IEC 61010-1 Hot Surface Warning"
Logo5: library part IEC_HighVoltage, "IEC 61010-1 High Voltage Warning"
Q1: library part CMP-0082232-1, "MOSFET, 2-CH, N-CH, 60 V, 49 A, AEC-Q101, 4.9x5.9mm", Alternate Manufacturer=None, Manufacturer=Vishay-Siliconix, Supplier Part Number 1=SQJB60EP-T1_GE3CT-ND, Value1="0.016 ohm", Value2="18 nC"
R1 R2: library part CMP-0025950-2, "RES, 100 k, 1%, 0.063 W, 0402", Manufacturer=Vishay-Dale, Power_W=63mW, Supplier Part Number 1=541-100KLCT-ND, TempCo="100 ppm/C", Tolerance_%=1%, Value2=0.063W, Value_Code=100k
R3: library part CMP-0027007-2, "RES, 0, 5%, 0.063 W, AEC-Q200 Grade 0, 0402", Manufacturer="Stackpole Electronics Inc", Power_W=63mW, Supplier Part Number 1=RMCF0402JT10R0CT-ND, TempCo="100 ppm/C", Tolerance_%=1%, Value2=0.063W, Value_Code=10R0, ValueDisplayed=10.0
R4 R5 R8 R11: library part CMP-0027007-2, "RES, 0, 5%, 0.063 W, AEC-Q200 Grade 0, 0402", Manufacturer="KOA Speer", Power_W=63mW, Supplier Part Number 1=660-RK73Z1ETTP, TempCo=ppm/C, Tolerance_%=5%, Value2=0.063W, Value_Code=0000, ValueDisplayed=0
R6: library part CMP-0015107-2, "RES, 0.004, 1%, 3 W, 2512 WIDE", Manufacturer="Susumu Co Ltd", Power_W=3W, Supplier Part Number 1=408-1616-1-ND, TempCo="50 ppm/C", Tolerance_%=1%, Value_Code=6L000, ValueDisplayed=0.006
R7: library part CMP-0026437-1, "RES, 51.1 k, 1%, 0.063 W, 0402", Manufacturer=Vishay-Dale, PartNumber=CRCW040251K1FKED, Power_W=63mW, Supplier Part Number 1=541-51.1KLCT-ND, TempCo="100 ppm/C", Tolerance_%=1%, Value2=0.063W, Value_Code=51k1, ValueDisplayed=51.1k
R9: library part CMP-0025743-3, "RES, 1.0, 5%, 0.1 W, 0603", Manufacturer=Vishay-Dale, Power_W=100mW, Supplier Part Number 1=541-1.0GCT-ND, TempCo="200 ppm/C", Tolerance_%=5%, Value2=0.1W, Value_Code=1R00, ValueDisplayed=1.0
R10: library part CMP-0026761-1, "RES, 49.9, 1%, 0.063 W, AEC-Q200 Grade 0, 0402", Manufacturer="Stackpole Electronics Inc", Power_W=63mW, Supplier Part Number 1=RMCF0402FT49R9CT-ND, TempCo="100 ppm/C", Tolerance_%=1%, Value2=0.063W, Value_Code=49R9, ValueDisplayed=49.9
R12: library part CMP-0026718-1, "RES, 49.9 k, 1%, 0.063 W, 0402", Manufacturer=Rohm, PartNumber=MCR01MZPF4992, Power_W=63mW, Supplier Part Number 1=RHM49.9KLCT-ND, TempCo="100 ppm/C", Tolerance_%=1%, Value2=0.063W, Value_Code=49k9, ValueDisplayed=49.9k
R13: library part CMP-0026162-2, "RES, 20.0 k, 1%, 0.063 W, AEC-Q200 Grade 0, 0402", Manufacturer=Vishay-Dale, Power_W=63mW, Supplier Part Number 1=541-5.49KLCT-ND, TempCo="100 ppm/C", Tolerance_%=1%, Value2=0.063W, Value_Code=5k49, ValueDisplayed=5.49k
R14 R15: library part CMP-0027002-2, "RES, 0, 5%, 0.063 W, 0402", Manufacturer=Rohm, PartNumber=MCR01MZPJ000, Power_W=63mW, Supplier Part Number 1=RHM0.0JCT-ND, TempCo="500 ppm/C", Tolerance_%=5%, Value2=0.063W, Value_Code=0000, ValueDisplayed=0
TP1 TP3 TP5 TP6 TP7 TP8 TP9: library part 1598-2, "Terminal, Turret, TH, Triple", Manufacturer=Keystone, Supplier Part Number 1=1598-2K-ND
TP2 TP4: library part CMP-0075188-1, "Test Lead clips and hooks, SMT", Current_A=2A, Manufacturer=Harwin, Supplier Part Number 1=S1751-46-ND
U1: library part CMP-0076290-1, "Wide Input 2.2MHz low Iq Synchronous Buck Controller, RGE0024J (VQFN-24)", Alternate Manufacturer="Texas Instruments"
ZX1 ZX2 ZX3: library part AssemblyNote, "This Assembly Note will show in the PcbDoc and associated outputs"

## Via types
v1: diameter 20, hole 10, Top Layer1 to Bottom Layer4, tented both sides, 647 vias
v2: diameter 16, hole 8, Top Layer1 to Bottom Layer4, tented both sides, 35 vias
v3: diameter 19.68, hole 7.87, Top Layer1 to Bottom Layer4, 5 vias

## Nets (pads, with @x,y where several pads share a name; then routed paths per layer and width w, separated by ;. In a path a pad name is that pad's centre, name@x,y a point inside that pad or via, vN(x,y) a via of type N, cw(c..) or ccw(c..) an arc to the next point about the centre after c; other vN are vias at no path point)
(BODE): EC1.1
(SoftStart): EC1.8
(SYNC/FPWM): EC1.4
(VCC): EC1.7
(VCCX): EC1.9
(VDDA): EC1.3
COMP: C33.1 R13.2 U1.20 | length 89
  Top Layer1 w10: U1.20@3394.8,970.47 3425.47,970.47 3437,982 C33.1@3443,982 ; R13.2@3472,982 R13.2@3477,977
  Top Layer1 w15: C33.1@3443,982 R13.2@3472,982
CS: C28.1 R10.2 U1.18 | length 94.9
  Top Layer1 w10: U1.18@3369.21,925.2 3377.11,917.3 3397.62,917.3 3404.06,910.86 3404.06,906.96 3436.02,875 R10.2@3441,875
DEMB: J1.2 J1.4 U1.1 | length 1427.9
  Top Layer1 w10: U1.1@3369.21,1074.8 v2(3382,1083) v2@3377.41,1083
  Layer3 w15: J1.2@3261.07,166.25 3310.32,117 3487,117 3511,141 3511,437 3543,469 3543,932 3392,1083 v2(3382,1083)
  Bottom Layer4 w70: J1.4@3161.07,166.25 J1.2@3261.07,166.25
DITH: C34.2 J4.2 J4.4 U1.5 | length 1778.1
  Top Layer1 w10: v2(3277,1104) 3277,1099.73 3290.47,1086.25 U1.5@3290.47,1074.8
  Layer3 w15: v2(3277,1104) 3293,1104 3340,1151 3675,1151 3725,1101 3725,193 3698.25,166.25 J4.2@3661.07,166.25
  Layer3 w50: J4.4@3561.07,166.25 J4.2@3661.07,166.25
  Bottom Layer4 w15: J4.2@3661.07,166.25 3680.82,186 C34.2@3725,186
  Bottom Layer4 w70: J4.4@3561.07,166.25 J4.2@3661.07,166.25
EN: C29.1 EC1.10 J2.2 J2.4 R12.2 U1.23 | length 7425.3
  Top Layer1 w10: U1.23@3394.8,1029.53 3501.47,1029.53 v2@3507.5,1023.5 ; R12.2@3513,1018 R12.2@3520,1011
  Top Layer1 w12: v2@3507.5,1023.5 3513,1018 R12.2@3513,1011
  Layer2 w15: v2(3510,1026) 3893,1026 3987,932 3987,861 v1(3986,860)
  Layer2 w30: J2.4@2961.07,166.25 2962,165.32 v1(2962,36)
  Layer3 w30: v1(362,1511) 172,1321 172,204 352,24 2069.91,24 2081.91,36 v1(2962,36) 3944,36 3966,58 3966,807 3986,827 v1(3986,860)
  Layer3 w40: J2.4@2961.07,166.25 J2.2@3061.07,166.25
  Bottom Layer4 w30: EC1.10@173,1557 219,1511 v1(362,1511)
  Bottom Layer4 w40: J2.2@3060.82,166 J2.2@3061.07,166.25
  Bottom Layer4 w70: C29.1@2881.43,165 J2.4@2961.07,166.25 ; J2.4@2961.07,166 J2.2@3060.82,166
FB: J3.2 J3.4 U1.19 | length 973
  Top Layer1 w15: v2(3395,939) U1.19@3395,947
  Layer3 w15: v2(3395,939) 3514,820 3514,529 3411,426 v1(3411,166)
  Bottom Layer4 w70: J3.4@3361.07,166.25 J3.2@3461.07,166.25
